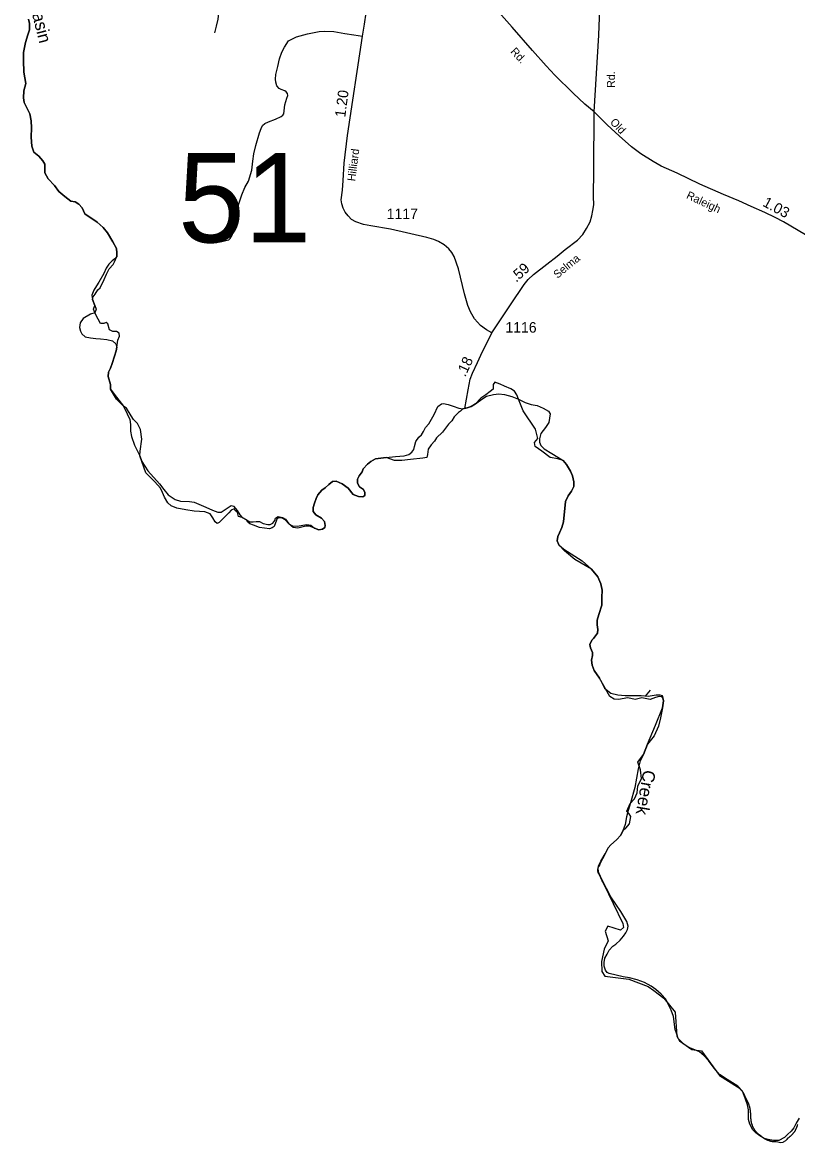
# Model space of a CAD drawing. Extents: x 2220236 to 2384410, y 720751 to 894131.
# Drawn here: x 2225880 to 2235115, y 721680 to 735017 of the extents above; entities that cross this region are included whole.
import ezdxf

# ---------------------------------------------------------------- set-up
doc = ezdxf.new("R2010")
doc.units = 0
doc.layers.add('Default', color=7, linetype='Continuous')

msp = doc.modelspace()

# ---------------------------------------------------------------- linework, layer by layer
at = {"layer": 'Default'}
for points in [[(2232693, 733952), (2232745, 734865), (2232758, 735180), (2232769, 735372), (2232787, 735735), (2232800, 735845), (2232836, 735982), (2232891, 736115), (2232922, 736173), (2232972, 736255), (2233128, 736464), (2233259, 736627), (2233354, 736750), (2233449, 736869), (2233524, 736977), (2233577, 737060), (2233638, 737170), (2233698, 737311), (2233737, 737444), (2233843, 737776), (2233909, 738007), (2233977, 738218), (2234110, 738639)], [(2228172, 734892), (2228193, 734973), (2228211, 735057), (2228221, 735133), (2228221, 735211), (2228216, 735287), (2228195, 735417), (2228159, 735610), (2228135, 735712), (2228078, 735879), (2228031, 736009), (2227984, 736135), (2227932, 736265), (2227903, 736359), (2227895, 736401)], [(2232693, 733952), (2232580, 734044), (2232441, 734173), (2232224, 734389), (2232120, 734502), (2231956, 734684), (2231715, 734959), (2231525, 735175), (2231310, 735417), (2231103, 735645), (2230880, 735871), (2230706, 736076), (2230532, 736280), (2230355, 736476)], [(2225952, 735057), (2225965, 735004), (2225963, 734929), (2225946, 734868), (2225917, 734779), (2225895, 734660), (2225895, 734562), (2225897, 734424), (2225920, 734290), (2225897, 734201), (2225895, 734121), (2225903, 734062), (2225931, 734001), (2225967, 733929), (2225986, 733846), (2225989, 733763), (2225986, 733651), (2225992, 733543), (2226017, 733474), (2226075, 733426), (2226122, 733368), (2226147, 733329), (2226147, 733268), (2226147, 733226), (2226186, 733154), (2226264, 733076), (2226314, 733004), (2226386, 732943), (2226458, 732890), (2226508, 732879), (2226553, 732852), (2226591, 732810), (2226622, 732738), (2226772, 732638), (2226843, 732574), (2226893, 732510), (2226956, 732404), (2227001, 732324), (2227006, 732274), (2227004, 732229), (2226981, 732202), (2226951, 732177), (2226909, 732140), (2226876, 732090), (2226851, 732029), (2226791, 731924), (2226761, 731882), (2226730, 731829), (2226708, 731771), (2226714, 731718), (2226741, 731646), (2226759, 731602), (2226743, 731560), (2226690, 731543), (2226604, 731491), (2226568, 731441), (2226562, 731385), (2226573, 731341), (2226587, 731310), (2226629, 731274), (2226690, 731263), (2226754, 731254), (2226809, 731249), (2226884, 731241), (2226954, 731224), (2226993, 731191), (2227004, 731149), (2226998, 731107), (2226976, 731043), (2226948, 730957), (2226931, 730902), (2226904, 730852), (2226901, 730802), (2226929, 730707), (2226929, 730652)], [(2226314, 733004), (2226264, 733076), (2226186, 733154), (2226147, 733226), (2226147, 733268), (2226147, 733329), (2226122, 733368), (2226075, 733426), (2226017, 733474), (2225992, 733543), (2225986, 733651), (2225989, 733763), (2225986, 733846), (2225967, 733929), (2225931, 734001), (2225903, 734062), (2225895, 734121), (2225897, 734201), (2225920, 734290), (2225897, 734424), (2225895, 734562), (2225895, 734660), (2225917, 734779), (2225946, 734868), (2225963, 734929), (2225965, 735004), (2225952, 735057)], [(2231473, 731321), (2231409, 731356), (2231336, 731410), (2231265, 731487), (2231217, 731572), (2231186, 731647), (2231147, 731786), (2231076, 732083), (2231024, 732230), (2230997, 732277), (2230960, 732320), (2230903, 732369), (2230838, 732407), (2230783, 732431), (2230696, 732456), (2230266, 732555), (2230030, 732597), (2229943, 732611), (2229853, 732642), (2229800, 732670), (2229759, 732713), (2229727, 732757), (2229701, 732805), (2229684, 732858), (2229679, 732906), (2229693, 733019), (2229703, 733134), (2229715, 733343), (2229751, 733670), (2229933, 734853), (2229954, 734998), (2229977, 735131)], [(2228239, 732404), (2228305, 732421), (2228340, 732430), (2228357, 732445), (2228373, 732477), (2228389, 732517), (2228418, 732644), (2228434, 732760), (2228449, 732835), (2228495, 732965), (2228531, 733052), (2228574, 733126), (2228612, 733256), (2228624, 733364), (2228636, 733451), (2228661, 733552), (2228704, 733701), (2228723, 733755), (2228742, 733790), (2228769, 733813), (2228810, 733835), (2228894, 733867), (2228963, 733896), (2228984, 733912), (2228993, 733928), (2228998, 733966), (2229005, 734037), (2229029, 734115), (2229041, 734147), (2229040, 734171), (2229024, 734192), (2229007, 734204), (2228963, 734218), (2228939, 734230), (2228913, 734262), (2228899, 734305), (2228895, 734342), (2228900, 734396), (2228921, 734491), (2228943, 734585), (2228971, 734662), (2229002, 734723), (2229051, 734796), (2229088, 734818), (2229147, 734847), (2229277, 734881), (2229414, 734907), (2229475, 734912), (2229592, 734907), (2229722, 734886), (2229830, 734869), (2229933, 734853)], [(2231473, 731321), (2231693, 731654), (2231858, 731896), (2231905, 731956), (2231968, 732017), (2232128, 732138), (2232251, 732233), (2232346, 732312), (2232491, 732423), (2232555, 732492), (2232602, 732565), (2232644, 732644), (2232665, 732715), (2232675, 732776), (2232686, 732847), (2232684, 732945), (2232687, 733258), (2232693, 733952)], [(2237320, 731171), (2237239, 731200), (2237164, 731231), (2236581, 731622), (2236257, 731826), (2236015, 731983), (2235674, 732207), (2235346, 732403), (2235208, 732489), (2234947, 732644), (2234848, 732694), (2234726, 732755), (2234563, 732825), (2234415, 732891), (2234232, 732967), (2233951, 733092), (2233680, 733221), (2233489, 733305), (2233393, 733362), (2233249, 733453), (2233138, 733536), (2232990, 733668), (2232847, 733797), (2232693, 733952)], [(2226929, 730652), (2226929, 730707), (2226901, 730802), (2226904, 730852), (2226931, 730902), (2226948, 730957), (2226976, 731043), (2226998, 731107), (2227004, 731149), (2227015, 731234), (2227037, 731283), (2227032, 731318), (2227002, 731336), (2226958, 731337), (2226917, 731358), (2226898, 731427), (2226877, 731445), (2226850, 731434), (2226812, 731434), (2226755, 731534), (2226729, 731603), (2226741, 731646), (2226714, 731718), (2226725, 731749), (2226748, 731781), (2226779, 731834), (2226806, 731857), (2226854, 731957), (2226880, 732020), (2226913, 732084), (2226960, 732134), (2226977, 732165), (2227004, 732229), (2227006, 732274), (2227001, 732324), (2226956, 732404), (2226893, 732510), (2226843, 732574), (2226772, 732638), (2226622, 732738), (2226591, 732810), (2226553, 732852), (2226508, 732879), (2226458, 732890), (2226386, 732943), (2226314, 733004)], [(2231149, 730422), (2231190, 730643), (2231215, 730768), (2231242, 730841), (2231301, 730968), (2231360, 731099), (2231421, 731215), (2231473, 731321)], [(2226929, 730652), (2227001, 730555), (2227086, 730449), (2227127, 730355), (2227160, 730291), (2227169, 730230), (2227169, 730152), (2227180, 730088), (2227216, 729982), (2227278, 729857), (2227303, 729788), (2227376, 729677), (2227512, 729524), (2227564, 729455), (2227617, 729394), (2227698, 729335), (2227764, 729316), (2227870, 729313), (2227927, 729307), (2228065, 729246), (2228146, 729208), (2228207, 729185), (2228249, 729185), (2228296, 729219), (2228369, 729266), (2228394, 729258), (2228417, 729230), (2228439, 729205), (2228469, 729155), (2228500, 729124), (2228550, 729096), (2228589, 729071), (2228630, 729071), (2228666, 729074), (2228705, 729074), (2228747, 729052), (2228802, 729038), (2228833, 729041), (2228863, 729055), (2228886, 729085), (2228897, 729113), (2228927, 729135), (2228980, 729124), (2229013, 729102), (2229055, 729049), (2229099, 729024), (2229155, 729019), (2229269, 729041), (2229316, 729030), (2229360, 728994), (2229410, 728977), (2229457, 728985), (2229482, 729005), (2229488, 729027), (2229478, 729074), (2229442, 729113), (2229376, 729155), (2229342, 729194), (2229342, 729241), (2229359, 729294), (2229381, 729349), (2229401, 729391), (2229448, 729446), (2229487, 729474), (2229531, 729516), (2229573, 729552), (2229617, 729555), (2229689, 729524), (2229759, 729471), (2229820, 729396), (2229884, 729371), (2229936, 729369), (2229958, 729385), (2229961, 729419), (2229942, 729457), (2229895, 729488), (2229872, 729530), (2229872, 729577), (2229890, 729619), (2229927, 729666), (2229940, 729702), (2229993, 729757), (2230032, 729791), (2230085, 729821), (2230215, 729838), (2230323, 729849), (2230429, 729857), (2230484, 729874), (2230521, 729899), (2230543, 729932), (2230551, 729969), (2230568, 730027), (2230604, 730080), (2230634, 730107), (2230659, 730146), (2230682, 730196), (2230720, 730238), (2230787, 730349), (2230830, 730446), (2230872, 730474), (2230897, 730480)], [(2229410, 728977), (2229360, 728994), (2229301, 729020), (2229255, 729018), (2229160, 728997), (2229105, 729003), (2229055, 729049), (2229009, 729093), (2228975, 729116), (2228938, 729118), (2228917, 729111), (2228908, 729092), (2228878, 729016), (2228855, 728998), (2228825, 728989), (2228764, 728995), (2228704, 729004), (2228635, 729031), (2228591, 729047), (2228566, 729066), (2228550, 729096), (2228500, 729124), (2228454, 729136), (2228443, 729182), (2228409, 729211), (2228401, 729226), (2228367, 729210), (2228339, 729180), (2228284, 729121), (2228226, 729064), (2228201, 729051), (2228177, 729072), (2228150, 729120), (2228116, 729167), (2228053, 729189), (2227926, 729199), (2227826, 729213), (2227720, 729235), (2227652, 729260), (2227611, 729296), (2227574, 729363), (2227550, 729422), (2227525, 729472), (2227456, 729548), (2227352, 729655), (2227303, 729788), (2227278, 729857), (2227283, 729912), (2227303, 730055), (2227287, 730172), (2227252, 730243), (2227203, 730290), (2227174, 730332), (2227119, 730424), (2227086, 730449), (2227003, 730531), (2226929, 730652)], [(2232770, 728333), (2232734, 728416), (2232659, 728508), (2232461, 728622), (2232338, 728727), (2232272, 728799), (2232250, 728844), (2232258, 728896), (2232278, 728941), (2232305, 729002), (2232325, 729071), (2232333, 729155), (2232340, 729230), (2232351, 729313), (2232382, 729380), (2232423, 729435), (2232448, 729491), (2232448, 729546), (2232432, 729619), (2232409, 729674), (2232360, 729752), (2232321, 729802), (2232257, 729820), (2232168, 729838), (2232066, 729913), (2231989, 729968), (2231982, 730014), (2232019, 730063), (2231993, 730176), (2231844, 730393), (2231790, 730530), (2231769, 730583), (2231742, 730625), (2231700, 730654), (2231625, 730687), (2231573, 730709), (2231510, 730733), (2231487, 730706), (2231489, 730652), (2231451, 730623), (2231401, 730584), (2231342, 730545), (2231277, 730474), (2231227, 730443), (2231180, 730427), (2231127, 730418), (2231100, 730389), (2231075, 730371), (2231023, 730322), (2230996, 730273)], [(2230897, 730480), (2230952, 730468), (2231013, 730449), (2231080, 730424), (2231127, 730418), (2231180, 730427), (2231227, 730443), (2231277, 730474), (2231352, 730530), (2231410, 730568), (2231491, 730588), (2231555, 730596), (2231624, 730588), (2231710, 730563), (2231790, 730530), (2231871, 730491), (2231940, 730468), (2232013, 730455), (2232085, 730424), (2232149, 730388), (2232169, 730357), (2232161, 730307), (2232150, 730255), (2232111, 730193), (2232058, 730124), (2232042, 730060), (2232042, 730019), (2232058, 729980), (2232097, 729941), (2232187, 729885), (2232260, 729841), (2232321, 729802), (2232360, 729752), (2232409, 729674), (2232432, 729619), (2232448, 729546), (2232448, 729491), (2232423, 729435), (2232382, 729380), (2232351, 729313), (2232340, 729230), (2232333, 729155), (2232325, 729071), (2232305, 729002), (2232278, 728941), (2232258, 728896), (2232250, 728844), (2232272, 728799), (2232330, 728744), (2232548, 728608), (2232659, 728508), (2232734, 728416), (2232770, 728333), (2232787, 728258), (2232784, 728169), (2232781, 728077), (2232748, 727966), (2232729, 727899), (2232729, 727844), (2232736, 727791), (2232730, 727747), (2232683, 727683), (2232663, 727663), (2232641, 727610), (2232647, 727569), (2232672, 727516), (2232672, 727480), (2232661, 727422), (2232666, 727363), (2232691, 727299), (2232755, 727211), (2232816, 727091), (2232891, 727030), (2232973, 727013), (2233059, 727005), (2233164, 727002), (2233251, 727002), (2233334, 726994), (2233431, 727011), (2233475, 727013), (2233500, 727002), (2233511, 726974), (2233517, 726938), (2233506, 726855), (2233481, 726738), (2233456, 726638), (2233406, 726522), (2233327, 726425), (2233280, 726300), (2233238, 726225), (2233216, 726130), (2233174, 725908), (2233123, 725727), (2233098, 725633), (2233076, 725558), (2233062, 725466), (2233034, 725391), (2233009, 725339), (2232959, 725286), (2232890, 725227), (2232859, 725191)], [(2230996, 730273), (2230958, 730234), (2230919, 730187), (2230886, 730137), (2230813, 730072), (2230788, 730033), (2230751, 729988), (2230715, 729935), (2230705, 729871), (2230697, 729835), (2230650, 729830), (2230504, 729815), (2230401, 729802), (2230311, 729800), (2230215, 729838), (2230085, 729821), (2230032, 729791), (2229993, 729757), (2229940, 729702), (2229927, 729666), (2229890, 729619), (2229872, 729577), (2229872, 729530), (2229895, 729488), (2229942, 729457), (2229961, 729419), (2229958, 729385), (2229936, 729369), (2229884, 729371), (2229820, 729396), (2229759, 729471), (2229689, 729524), (2229617, 729555), (2229573, 729552), (2229531, 729516), (2229487, 729474), (2229448, 729446), (2229401, 729391), (2229381, 729349), (2229359, 729294), (2229342, 729241), (2229342, 729194), (2229376, 729155), (2229442, 729113), (2229478, 729074), (2229488, 729027), (2229482, 729005), (2229457, 728985), (2229410, 728977)], [(2232859, 725191), (2232890, 725227), (2232959, 725286), (2233009, 725339), (2233034, 725391), (2233070, 725422), (2233111, 725474), (2233130, 725564), (2233109, 725594), (2233079, 725626), (2233122, 725716), (2233171, 725772), (2233205, 725845), (2233212, 725922), (2233255, 726017), (2233244, 726120), (2233212, 726210), (2233280, 726300), (2233327, 726425), (2233422, 726652), (2233506, 726855), (2233517, 726938), (2233511, 726974), (2233493, 726987), (2233467, 726991), (2233422, 726978), (2233360, 726955), (2233261, 726976), (2233180, 726957), (2233092, 726974), (2232980, 726955), (2232929, 726961), (2232877, 726991), (2232755, 727211), (2232691, 727299), (2232666, 727363), (2232661, 727422), (2232672, 727480), (2232672, 727516), (2232647, 727569), (2232641, 727610), (2232663, 727663), (2232683, 727683), (2232730, 727747), (2232736, 727791), (2232729, 727844), (2232729, 727899), (2232748, 727966), (2232781, 728077), (2232784, 728169), (2232787, 728258), (2232770, 728333)], [(2233360, 727068), (2233299, 726997)], [(2232859, 725191), (2232789, 725059), (2232760, 724997), (2232755, 724981), (2232753, 724979), (2232752, 724977), (2232750, 724975), (2232749, 724973), (2232747, 724971), (2232746, 724969), (2232744, 724967), (2232743, 724964), (2232742, 724962), (2232741, 724960), (2232740, 724957), (2232739, 724955), (2232737, 724953), (2232737, 724950), (2232736, 724948), (2232735, 724945), (2232734, 724943), (2232734, 724941), (2232734, 724938), (2232733, 724935), (2232733, 724933), (2232733, 724930), (2232732, 724928), (2232732, 724925), (2232732, 724923), (2232732, 724920), (2232732, 724918), (2232733, 724915), (2232733, 724913), (2232733, 724910), (2232734, 724908), (2232734, 724905), (2232735, 724903), (2232735, 724900), (2232736, 724898), (2232737, 724895), (2232738, 724893), (2232739, 724891), (2232740, 724888), (2232741, 724886), (2232742, 724884), (2232744, 724882), (2232745, 724879), (2232747, 724877), (2232748, 724875), (2232750, 724873), (2232781, 724802), (2232783, 724797), (2232801, 724764), (2233033, 724288), (2233040, 724241), (2233007, 724208), (2232856, 724257), (2232824, 724197), (2232857, 724082), (2232810, 723983), (2232777, 723838), (2232781, 723718), (2232820, 723662), (2233106, 723624), (2233336, 723538), (2233401, 723489), (2233520, 723400), (2233658, 723233), (2233678, 722948), (2233708, 722890), (2233854, 722790), (2233969, 722774), (2234185, 722479), (2234398, 722344), (2234401, 722342), (2234404, 722339), (2234407, 722337), (2234411, 722335), (2234414, 722333), (2234417, 722330), (2234420, 722328), (2234423, 722325), (2234426, 722323)], [(2235133, 721970), (2235099, 721911), (2235069, 721856), (2235038, 721817), (2234994, 721778), (2234958, 721742), (2234892, 721706), (2234829, 721706), (2234765, 721717), (2234715, 721728), (2234665, 721761), (2234618, 721795), (2234582, 721833), (2234545, 721900), (2234529, 721956), (2234529, 722011), (2234529, 722069), (2234518, 722128), (2234493, 722197), (2234459, 722292), (2234401, 722350), (2234276, 722431), (2234186, 722489), (2234119, 722567), (2234053, 722656), (2233997, 722717), (2233947, 722761), (2233889, 722786), (2233820, 722811), (2233772, 722844), (2233731, 722878), (2233692, 722919), (2233675, 722972), (2233657, 723025), (2233635, 723180), (2233607, 723255), (2233574, 723330), (2233546, 723389), (2233491, 723447), (2233427, 723503), (2233369, 723544), (2233291, 723586), (2233205, 723619), (2233113, 723642), (2233035, 723655), (2232870, 723692), (2232845, 723705), (2232826, 723733), (2232812, 723780), (2232812, 723825), (2232820, 723875), (2232845, 723925), (2232870, 723972), (2232915, 724019), (2232948, 724044), (2233001, 724089), (2233040, 724136), (2233067, 724178), (2233087, 724216), (2233096, 724258), (2233080, 724314), (2233008, 724430), (2232891, 724605), (2232788, 724805), (2232747, 724891), (2232738, 724939), (2232744, 724972), (2232772, 725030), (2232823, 725119), (2232859, 725191)], [(2234426, 722323), (2234429, 722320), (2234432, 722318), (2234435, 722315), (2234438, 722312), (2234440, 722309), (2234443, 722306), (2234446, 722303), (2234448, 722300), (2234451, 722297), (2234453, 722294), (2234455, 722291), (2234458, 722288), (2234460, 722285), (2234462, 722281), (2234464, 722278), (2234466, 722275), (2234468, 722271), (2234470, 722268), (2234472, 722264), (2234474, 722261), (2234476, 722257), (2234477, 722254), (2234479, 722250), (2234480, 722247), (2234482, 722243), (2234483, 722239), (2234484, 722236), (2234486, 722232), (2234487, 722228), (2234528, 722144), (2234530, 722139), (2234532, 722134), (2234534, 722129), (2234535, 722124), (2234537, 722119), (2234538, 722114), (2234540, 722109), (2234541, 722104), (2234542, 722099), (2234544, 722094), (2234544, 722089), (2234545, 722084), (2234546, 722079), (2234547, 722074), (2234548, 722069), (2234549, 722064), (2234550, 722058), (2234550, 722053), (2234551, 722048), (2234551, 722043), (2234551, 722038), (2234552, 722033), (2234552, 722027), (2234552, 722022), (2234552, 722017), (2234552, 722012), (2234552, 722001), (2234553, 721991), (2234554, 721980), (2234555, 721970), (2234556, 721959), (2234557, 721949), (2234557, 721944), (2234558, 721940), (2234559, 721935), (2234560, 721931), (2234561, 721926), (2234562, 721921), (2234563, 721917), (2234564, 721913), (2234566, 721908), (2234567, 721904), (2234568, 721899), (2234570, 721895), (2234572, 721890), (2234574, 721886), (2234575, 721882), (2234577, 721877), (2234579, 721873), (2234581, 721869), (2234583, 721865), (2234585, 721861), (2234587, 721856), (2234590, 721852), (2234592, 721848), (2234594, 721844), (2234597, 721840), (2234599, 721836), (2234602, 721833), (2234604, 721829)], [(2234604, 721829), (2234607, 721825), (2234610, 721821), (2234613, 721818), (2234616, 721814), (2234619, 721810), (2234622, 721807), (2234625, 721803), (2234628, 721800), (2234631, 721797), (2234635, 721793), (2234640, 721789), (2234646, 721785), (2234651, 721781), (2234657, 721777), (2234662, 721772), (2234667, 721768), (2234673, 721764), (2234678, 721759), (2234683, 721755), (2234688, 721750), (2234693, 721745), (2234697, 721743), (2234701, 721740), (2234705, 721737), (2234708, 721735), (2234713, 721732), (2234716, 721730), (2234720, 721728), (2234724, 721725), (2234729, 721723), (2234732, 721721), (2234737, 721719), (2234741, 721717), (2234745, 721715), (2234749, 721713), (2234754, 721711), (2234758, 721710), (2234762, 721708), (2234767, 721707), (2234771, 721705), (2234776, 721704), (2234780, 721702), (2234785, 721701), (2234789, 721700), (2234794, 721699), (2234798, 721698), (2234803, 721697), (2234807, 721696), (2234812, 721695), (2234816, 721695), (2234821, 721694), (2234826, 721694), (2234830, 721693), (2234835, 721693), (2234839, 721692), (2234844, 721692), (2234849, 721692), (2234853, 721692), (2234858, 721692), (2234916, 721680), (2234942, 721687), (2234946, 721688), (2234973, 721704), (2234989, 721720), (2234993, 721722), (2234994, 721731), (2235002, 721736), (2235006, 721738), (2235010, 721741), (2235014, 721744), (2235017, 721747), (2235021, 721749), (2235024, 721752), (2235028, 721755)], [(2235028, 721755), (2235032, 721758), (2235035, 721761), (2235039, 721764), (2235042, 721768), (2235045, 721771), (2235048, 721774), (2235052, 721777), (2235055, 721781), (2235058, 721784), (2235061, 721788), (2235064, 721791), (2235067, 721795), (2235070, 721799), (2235072, 721803), (2235075, 721806), (2235078, 721810), (2235080, 721814), (2235083, 721818), (2235085, 721822), (2235088, 721826), (2235090, 721830), (2235092, 721834), (2235094, 721838), (2235096, 721842), (2235098, 721846), (2235101, 721850), (2235102, 721855), (2235104, 721859), (2235106, 721863), (2235107, 721868), (2235109, 721872), (2235111, 721876), (2235112, 721881), (2235113, 721885), (2235115, 721890), (2235116, 721894)]]:
    msp.add_lwpolyline(points, dxfattribs=at)

# ---------------------------------------------------------------- texts
for s, height, rotation, p in [('Moccasin', 150, 284.2153, (2225876, 735580)), ('Rd.', 95, 313.2204, (2231688, 734664)), ('Rd.', 95, 89.2437, (2232938, 734236)), ('1.20', 125, 82.6915, (2229726, 733881)), ('Old', 95, 312.6636, (2232874, 733824)), ('Hilliard', 95, 82.6915, (2229844, 733122)), ('Raleigh', 95, 334.989, (2233781, 732926)), ('1.03', 125, 331.7377, (2234689, 732837)), ('Selma', 95, 39.5642, (2232254, 731963)), ('.59', 125, 42.4655, (2231763, 731917)), ('.18', 125, 64.9967, (2231155, 730789)), ('Creek', 150, 260.1114, (2233278, 726124))]:
    msp.add_text(s, height=height, rotation=rotation, dxfattribs=at).set_placement(p)
for s, height, p in [('51', 1066.3, (2227735, 732398)), ('1117', 125, (2230220, 732676)), ('1116', 125, (2231634, 731324))]:
    msp.add_text(s, height=height, dxfattribs=at).set_placement(p)

doc.saveas('drawing.dxf')
